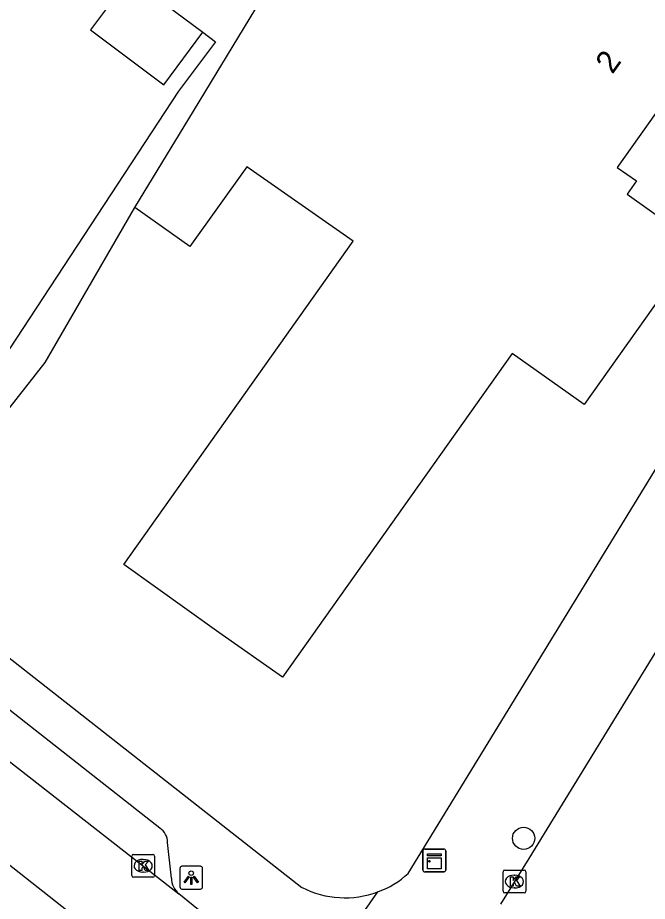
# Model space of a CAD drawing. Extents: x 162812 to 163818, y 381639 to 382470.
# Drawn here: x 163059.97 to 163087.58, y 381902.36 to 381941.12 of the extents above; entities that cross this region are included whole.
import ezdxf

# ---------------------------------------------------------------- set-up
doc = ezdxf.new("R2010")
doc.units = 0
for name, color, linetype in [('IMGEO_Boom', 7, 'Continuous'), ('IMGEO_Kast', 7, 'Continuous'), ('IMGEO_Kolk', 7, 'Continuous'), ('IMGEO_Lichtpunt', 7, 'Continuous'), ('IMGEO_Pand', 7, 'Continuous'), ('IMGEO_Pand_nummerreeks', 7, 'Continuous'), ('IMGEO_Rijbaan_lokaal_open', 7, 'Continuous'), ('IMGEO_Voetpad_open', 7, 'Continuous')]:
    doc.layers.add(name, color=color, linetype=linetype)

msp = doc.modelspace()

# ---------------------------------------------------------------- linework, layer by layer
at = {"layer": 'IMGEO_Boom'}
msp.add_circle((163082.156, 381905.126), 0.489, dxfattribs=at)
at = {"layer": 'IMGEO_Kast'}
for p, q in [((163077.743, 381903.73), (163077.743, 381904.571)), ((163077.743, 381904.571), (163077.743, 381903.73)), ((163077.818, 381904.655), (163078.659, 381904.655)), ((163078.659, 381904.655), (163077.818, 381904.655)), ((163078.743, 381904.58), (163078.743, 381903.739)), ((163078.743, 381903.739), (163078.743, 381904.58)), ((163078.668, 381903.655), (163077.827, 381903.655)), ((163077.827, 381903.655), (163078.668, 381903.655))]:
    msp.add_line(p, q, dxfattribs=at)
for points in [[(163077.938, 381904.445), (163078.538, 381904.445), (163078.538, 381904.36), (163077.938, 381904.36), (163077.938, 381904.445)], [(163077.938, 381904.27), (163078.538, 381904.27), (163078.538, 381903.781), (163077.938, 381903.781), (163077.938, 381904.27)]]:
    msp.add_lwpolyline(points, dxfattribs=at)
msp.add_circle((163078.022, 381904.119), 0.0377, dxfattribs=at)
for centre, start, end in [((163077.821, 381904.577), 92.4484, 184.2845), ((163077.821, 381904.577), 92.4484, 184.2845), ((163078.665, 381904.577), 2.4484, 94.2845), ((163078.665, 381904.577), 2.4484, 94.2845), ((163077.821, 381903.733), 182.4484, 274.2845), ((163077.821, 381903.733), 182.4484, 274.2845), ((163078.665, 381903.733), 272.4484, 4.2845), ((163078.665, 381903.733), 272.4484, 4.2845)]:
    msp.add_arc(centre, 0.0779, start, end, dxfattribs=at)
at = {"layer": 'IMGEO_Kolk'}
for p, q in [((163064.969, 381903.492), (163064.969, 381904.344)), ((163065.044, 381904.418), (163065.896, 381904.418)), ((163065.457, 381904.198), (163065.482, 381904.198)), ((163065.97, 381904.344), (163065.97, 381903.492)), ((163065.896, 381903.418), (163065.044, 381903.418)), ((163065.48, 381903.638), (163065.455, 381903.638)), ((163081.254, 381902.804), (163081.254, 381903.656)), ((163081.329, 381903.73), (163082.181, 381903.73)), ((163081.742, 381903.51), (163081.767, 381903.51)), ((163082.255, 381903.656), (163082.255, 381902.804)), ((163082.181, 381902.73), (163081.329, 381902.73)), ((163081.765, 381902.95), (163081.74, 381902.95))]:
    msp.add_line(p, q, dxfattribs=at)
for points in [[(163064.969, 381903.492), (163064.969, 381904.344)], [(163065.044, 381904.418), (163065.896, 381904.418)], [(163065.97, 381904.344), (163065.97, 381903.492)], [(163065.29, 381904.118), (163065.413, 381904.118), (163065.413, 381903.967), (163065.543, 381904.118), (163065.707, 381904.118), (163065.561, 381903.967), (163065.714, 381903.718), (163065.562, 381903.718), (163065.477, 381903.882), (163065.413, 381903.815), (163065.413, 381903.718), (163065.29, 381903.718), (163065.29, 381904.118)], [(163065.896, 381903.418), (163065.044, 381903.418)], [(163081.254, 381902.804), (163081.254, 381903.656)], [(163081.329, 381903.73), (163082.181, 381903.73)], [(163081.575, 381903.43), (163081.698, 381903.43), (163081.698, 381903.279), (163081.828, 381903.43), (163081.992, 381903.43), (163081.846, 381903.279), (163081.999, 381903.03), (163081.847, 381903.03), (163081.762, 381903.194), (163081.698, 381903.127), (163081.698, 381903.03), (163081.575, 381903.03), (163081.575, 381903.43)], [(163082.255, 381903.656), (163082.255, 381902.804)], [(163082.181, 381902.73), (163081.329, 381902.73)]]:
    msp.add_lwpolyline(points, dxfattribs=at)
for centre, start, end in [((163065.046, 381904.342), 91.552, 178.448), ((163065.046, 381904.342), 91.552, 178.448), ((163065.894, 381904.342), 1.552, 88.448), ((163065.894, 381904.342), 1.552, 88.448), ((163065.046, 381903.494), 181.552, 268.448), ((163065.046, 381903.494), 181.552, 268.448), ((163065.894, 381903.494), 271.552, 358.448), ((163065.894, 381903.494), 271.552, 358.448), ((163081.331, 381903.654), 91.552, 178.448), ((163081.331, 381903.654), 91.552, 178.448), ((163082.179, 381903.654), 1.552, 88.448), ((163082.179, 381903.654), 1.552, 88.448), ((163081.331, 381902.806), 181.552, 268.448), ((163081.331, 381902.806), 181.552, 268.448), ((163082.179, 381902.806), 271.552, 358.448), ((163082.179, 381902.806), 271.552, 358.448)]:
    msp.add_arc(centre, 0.0765, start, end, dxfattribs=at)
for centre, major_axis, ratio, start_param, end_param in [((163065.456, 381903.918), (-0.387, 0.002), 0.722429, 4.712389, 7.853982), ((163065.481, 381903.918), (-0.39, 0.002), 0.717154, 1.570796, 4.712389), ((163081.741, 381903.23), (-0.387, 0.002), 0.722429, 4.712389, 7.853982), ((163081.766, 381903.23), (-0.39, 0.002), 0.717154, 1.570796, 4.712389)]:
    msp.add_ellipse(centre, major_axis=major_axis, ratio=ratio, start_param=start_param, end_param=end_param, dxfattribs=at)
at = {"layer": 'IMGEO_Lichtpunt'}
for p, q in [((163067.079, 381903.801), (163067.079, 381902.994)), ((163067.079, 381903.801), (163067.079, 381902.994)), ((163067.981, 381903.896), (163067.173, 381903.896)), ((163067.981, 381903.896), (163067.173, 381903.896)), ((163068.075, 381902.994), (163068.075, 381903.801)), ((163068.075, 381902.994), (163068.075, 381903.801)), ((163067.173, 381902.9), (163067.981, 381902.9)), ((163067.173, 381902.9), (163067.981, 381902.9))]:
    msp.add_line(p, q, dxfattribs=at)
for points in [[(163067.453, 381903.465), (163067.492, 381903.437), (163067.304, 381903.175), (163067.266, 381903.202), (163067.453, 381903.465)], [(163067.555, 381903.417), (163067.602, 381903.417), (163067.602, 381903.095), (163067.555, 381903.095), (163067.555, 381903.417)], [(163067.665, 381903.437), (163067.703, 381903.464), (163067.89, 381903.202), (163067.851, 381903.174), (163067.665, 381903.437)]]:
    msp.add_lwpolyline(points, dxfattribs=at)
msp.add_circle((163067.578, 381903.599), 0.0994, dxfattribs=at)
for centre, start, end in [((163067.173, 381903.801), 90, 180), ((163067.173, 381903.801), 90, 180), ((163067.981, 381903.801), 0, 90), ((163067.981, 381903.801), 0, 90), ((163067.173, 381902.994), 180, 270), ((163067.173, 381902.994), 180, 270), ((163067.981, 381902.994), 270, 0), ((163067.981, 381902.994), 270, 360)]:
    msp.add_arc(centre, 0.0946, start, end, dxfattribs=at)
at = {"layer": 'IMGEO_Pand'}
for points in [[(163065.11, 381932.788), (163067.467, 381936.682), (163071.809, 381943.852)], [(163064.872, 381942.883), (163063.154, 381940.589), (163066.37, 381938.181), (163068.089, 381940.477)], [(163064.872, 381942.883), (163068.089, 381940.477)], [(163090.268, 381940.191), (163086.264, 381934.555), (163087.107, 381933.956), (163086.694, 381933.374), (163089.795, 381931.17), (163084.809, 381924.15), (163081.654, 381926.393), (163071.588, 381912.193), (163068.793, 381914.153), (163064.627, 381917.13), (163074.684, 381931.316), (163070.011, 381934.582), (163067.516, 381931.076), (163065.11, 381932.788)]]:
    msp.add_lwpolyline(points, dxfattribs=at)
at = {"layer": 'IMGEO_Rijbaan_lokaal_open'}
for points in [[(163109.12, 381947.814), (163082.385, 381904.243), (163081.136, 381902.235)], [(163018.389, 381940.704), (163067.037, 381902.692)], [(163069.543, 381896.09), (163067.173, 381897.988), (163058.977, 381904.423), (163054.221, 381908.123)], [(163071.739, 381898.909), (163069.313, 381900.831), (163067.037, 381902.692)]]:
    msp.add_lwpolyline(points, dxfattribs=at)
at = {"layer": 'IMGEO_Voetpad_open'}
for points in [[(163077.097, 381903.586), (163100.016, 381941.018), (163103.794, 381946.952)], [(163068.089, 381940.477), (163068.646, 381940.06), (163067.014, 381937.903), (163059.296, 381926.12)], [(163054.275, 381917.204), (163061.171, 381926), (163065.11, 381932.788)], [(163054.275, 381917.204), (163072.436, 381902.972)], [(163066.194, 381905.567), (163056.683, 381913.047)], [(163066.706, 381903.382), (163066.537, 381904.935)], [(163072.605, 381898.25), (163075.762, 381902.772)]]:
    msp.add_lwpolyline(points, dxfattribs=at)
for centre, radius, start, end in [((163065.854, 381904.973), 0.684, 356.8024, 60.1769), ((163067.601, 381903.387), 0.895, 180.3281, 230.9269), ((163074.319, 381906.641), 4.129, 290.4582, 312.2863), ((163074.326, 381906.639), 4.125, 242.7409, 290.3768)]:
    msp.add_arc(centre, radius, start, end, dxfattribs=at)

# ---------------------------------------------------------------- texts
at = {"layer": 'IMGEO_Pand_nummerreeks'}
msp.add_text('2', height=1, rotation=54.6086, dxfattribs=at).set_placement((163086.052, 381938.607))

doc.saveas('drawing.dxf')
